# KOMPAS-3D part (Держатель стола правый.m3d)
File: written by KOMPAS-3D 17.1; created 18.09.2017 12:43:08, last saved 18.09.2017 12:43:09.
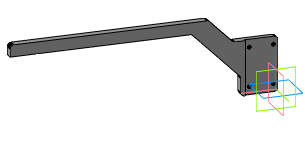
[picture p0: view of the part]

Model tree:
1. Операция без истории:1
